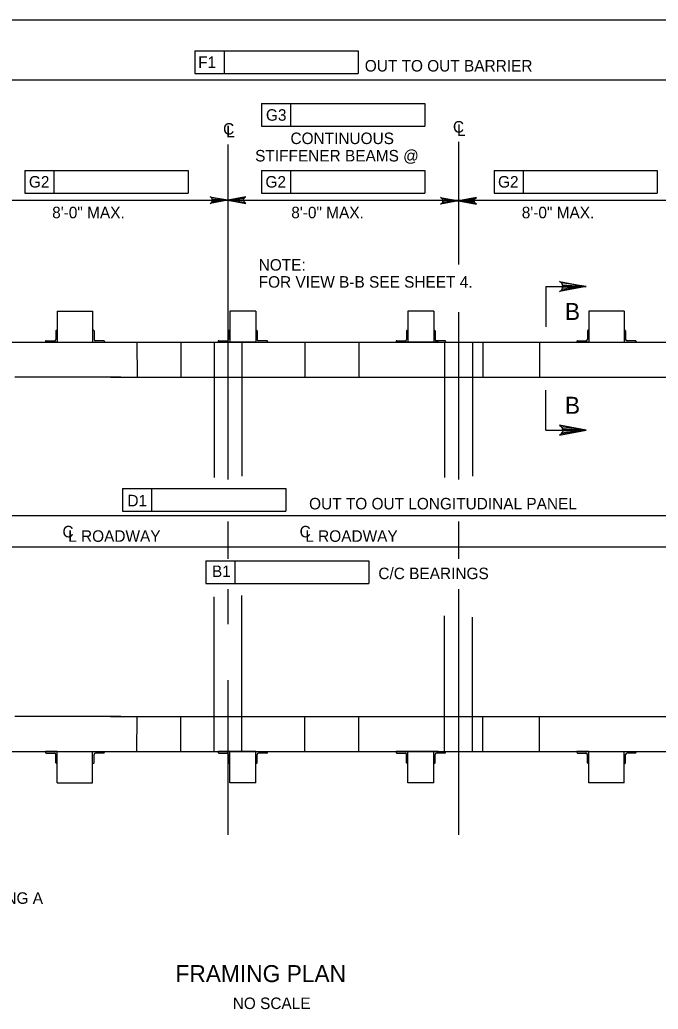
# Model space of a CAD drawing. Extents: x 638268 to 640277, y 295465 to 298435.
# Drawn here: x 639470.3 to 639636.6, y 297568.6 to 297826.5 of the extents above; entities that cross this region are included whole.
import ezdxf

# ---------------------------------------------------------------- set-up
doc = ezdxf.new("R2010")
doc.units = 0
doc.layers.add('2', color=7, linetype='Continuous')
doc.layers.add('4', color=7, linetype='Continuous')

msp = doc.modelspace()

# ---------------------------------------------------------------- linework, layer by layer
at = {"layer": '2'}
for p, q in [((639316.46, 297826.46), (640102.46, 297826.46)), ((639607.37, 297756.95), (639607.37, 297746.46)), ((639607.37, 297756.95), (639617.86, 297756.95)), ((639480.06, 297750.53), (639489.29, 297750.53)), ((639480.06, 297750.53), (639480.06, 297742.44)), ((639489.29, 297750.53), (639489.29, 297742.44)), ((639531.78, 297750.53), (639525.05, 297750.53)), ((639525.05, 297750.53), (639525.05, 297742.44)), ((639531.78, 297750.53), (639531.78, 297742.44)), ((639578.14, 297750.53), (639571.41, 297750.53)), ((639578.14, 297750.53), (639571.41, 297750.53)), ((639571.41, 297750.53), (639571.41, 297742.44)), ((639578.14, 297750.53), (639578.14, 297742.44)), ((639627.77, 297750.53), (639618.53, 297750.53)), ((639618.53, 297750.53), (639618.53, 297742.44)), ((639627.77, 297750.53), (639627.77, 297742.44)), ((639479.69, 297745.35), (639479.69, 297743.17)), ((639479.87, 297745.53), (639480.06, 297745.53)), ((639480.06, 297745.53), (639480.06, 297742.44)), ((639489.48, 297745.53), (639489.29, 297745.53)), ((639489.29, 297745.53), (639489.29, 297742.44)), ((639489.66, 297745.35), (639489.66, 297743.17)), ((639524.69, 297745.35), (639524.69, 297743.17)), ((639524.87, 297745.53), (639525.05, 297745.53)), ((639525.05, 297745.53), (639525.05, 297742.44)), ((639531.96, 297745.53), (639531.78, 297745.53)), ((639531.78, 297745.53), (639531.78, 297742.44)), ((639532.14, 297745.35), (639532.14, 297743.17)), ((639571.05, 297745.35), (639571.05, 297743.17)), ((639571.23, 297745.53), (639571.41, 297745.53)), ((639571.41, 297745.53), (639571.41, 297742.44)), ((639578.32, 297745.53), (639578.14, 297745.53)), ((639578.14, 297745.53), (639578.14, 297742.44)), ((639578.51, 297745.35), (639578.51, 297743.17)), ((639618.17, 297745.35), (639618.17, 297743.17)), ((639618.35, 297745.53), (639618.53, 297745.53)), ((639618.53, 297745.53), (639618.53, 297742.44)), ((639627.95, 297745.53), (639627.77, 297745.53)), ((639627.77, 297745.53), (639627.77, 297742.44)), ((639628.13, 297745.35), (639628.13, 297743.17)), ((639457.3, 297742.44), (639650.54, 297742.44)), ((639476.97, 297742.63), (639476.97, 297742.44)), ((639480.06, 297742.44), (639476.97, 297742.44)), ((639477.15, 297742.81), (639479.33, 297742.81)), ((639480.06, 297742.44), (639489.29, 297742.44)), ((639489.29, 297742.44), (639492.38, 297742.44)), ((639492.2, 297742.81), (639490.02, 297742.81)), ((639492.38, 297742.63), (639492.38, 297742.44)), ((639500.84, 297742.44), (639500.85, 297733.32)), ((639512.24, 297742.44), (639512.24, 297733.32)), ((639520.91, 297742.44), (639520.91, 297707.2)), ((639521.96, 297742.63), (639521.96, 297742.44)), ((639525.05, 297742.44), (639521.96, 297742.44)), ((639522.14, 297742.81), (639524.32, 297742.81)), ((639531.78, 297742.44), (639525.05, 297742.44)), ((639528.12, 297742.44), (639528.12, 297707.55)), ((639531.78, 297742.44), (639534.87, 297742.44)), ((639534.69, 297742.81), (639532.51, 297742.81)), ((639534.87, 297742.63), (639534.87, 297742.44)), ((639544.58, 297742.44), (639544.58, 297733.32)), ((639558.61, 297742.44), (639558.61, 297733.32)), ((639568.32, 297742.63), (639568.32, 297742.44)), ((639571.41, 297742.44), (639568.32, 297742.44)), ((639568.51, 297742.81), (639570.69, 297742.81)), ((639579.4, 297742.44), (639570.16, 297742.44)), ((639578.14, 297742.44), (639571.41, 297742.44)), ((639578.14, 297742.44), (639581.23, 297742.44)), ((639581.05, 297742.81), (639578.87, 297742.81)), ((639580.99, 297742.44), (639580.99, 297707.2)), ((639581.23, 297742.63), (639581.23, 297742.44)), ((639588.2, 297742.44), (639588.2, 297707.55)), ((639590.95, 297742.44), (639590.95, 297733.32)), ((639605.73, 297742.44), (639605.73, 297733.32)), ((639615.44, 297742.63), (639615.44, 297742.44)), ((639618.53, 297742.44), (639615.44, 297742.44)), ((639615.63, 297742.81), (639617.81, 297742.81)), ((639618.54, 297742.44), (639627.77, 297742.44)), ((639627.77, 297742.44), (639630.86, 297742.44)), ((639630.68, 297742.81), (639628.5, 297742.81)), ((639630.86, 297742.63), (639630.86, 297742.44)), ((639496.62, 297733.32), (639468.98, 297733.32)), ((639493.95, 297733.32), (639638.86, 297733.32)), ((639607.37, 297719.47), (639607.37, 297729.96)), ((639607.37, 297719.47), (639617.86, 297719.47)), ((639520.91, 297635.88), (639520.91, 297676.03)), ((639528.12, 297635.88), (639528.12, 297676.44)), ((639580.99, 297635.88), (639580.99, 297671.12)), ((639588.2, 297635.88), (639588.2, 297670.78)), ((639496.62, 297644.84), (639468.98, 297644.84)), ((639493.95, 297644.84), (639638.86, 297644.84)), ((639500.84, 297635.72), (639500.85, 297644.84)), ((639512.24, 297635.72), (639512.24, 297644.84)), ((639544.58, 297635.72), (639544.58, 297644.84)), ((639558.61, 297635.72), (639558.61, 297644.84)), ((639590.95, 297635.72), (639590.95, 297644.84)), ((639605.73, 297635.72), (639605.73, 297644.84)), ((639457.3, 297635.72), (639650.54, 297635.72)), ((639476.97, 297635.54), (639476.97, 297635.72)), ((639480.06, 297635.72), (639476.97, 297635.72)), ((639477.15, 297635.35), (639479.33, 297635.35)), ((639479.69, 297632.81), (639479.69, 297634.99)), ((639480.06, 297635.72), (639489.29, 297635.72)), ((639480.06, 297632.63), (639480.06, 297635.72)), ((639480.06, 297627.63), (639480.06, 297635.72)), ((639489.29, 297635.72), (639492.38, 297635.72)), ((639489.29, 297632.63), (639489.29, 297635.72)), ((639489.29, 297627.63), (639489.29, 297635.72)), ((639489.66, 297632.81), (639489.66, 297634.99)), ((639492.2, 297635.35), (639490.02, 297635.35)), ((639492.38, 297635.54), (639492.38, 297635.72)), ((639521.96, 297635.54), (639521.96, 297635.72)), ((639525.05, 297635.72), (639521.96, 297635.72)), ((639522.14, 297635.35), (639524.32, 297635.35)), ((639524.69, 297632.81), (639524.69, 297634.99)), ((639531.78, 297635.72), (639525.05, 297635.72)), ((639525.05, 297632.63), (639525.05, 297635.72)), ((639525.05, 297627.63), (639525.05, 297635.72)), ((639531.78, 297632.63), (639531.78, 297635.72)), ((639531.78, 297635.72), (639534.87, 297635.72)), ((639531.78, 297627.63), (639531.78, 297635.72)), ((639532.14, 297632.81), (639532.14, 297634.99)), ((639534.69, 297635.35), (639532.51, 297635.35)), ((639534.87, 297635.54), (639534.87, 297635.72)), ((639568.32, 297635.54), (639568.32, 297635.72)), ((639571.41, 297635.72), (639568.32, 297635.72)), ((639568.51, 297635.35), (639570.69, 297635.35)), ((639579.4, 297635.72), (639570.16, 297635.72)), ((639571.05, 297632.81), (639571.05, 297634.99)), ((639578.14, 297635.72), (639571.41, 297635.72)), ((639571.41, 297632.63), (639571.41, 297635.72)), ((639571.41, 297627.63), (639571.41, 297635.72)), ((639578.14, 297632.63), (639578.14, 297635.72)), ((639578.14, 297635.72), (639581.23, 297635.72)), ((639578.14, 297627.63), (639578.14, 297635.72)), ((639578.51, 297632.81), (639578.51, 297634.99)), ((639581.05, 297635.35), (639578.87, 297635.35)), ((639581.23, 297635.54), (639581.23, 297635.72)), ((639615.44, 297635.54), (639615.44, 297635.72)), ((639618.53, 297635.72), (639615.44, 297635.72)), ((639615.63, 297635.35), (639617.81, 297635.35)), ((639618.17, 297632.81), (639618.17, 297634.99)), ((639618.53, 297632.63), (639618.53, 297635.72)), ((639618.53, 297627.63), (639618.53, 297635.72)), ((639618.54, 297635.72), (639627.77, 297635.72)), ((639627.77, 297632.63), (639627.77, 297635.72)), ((639627.77, 297635.72), (639630.86, 297635.72)), ((639627.77, 297627.63), (639627.77, 297635.72)), ((639628.13, 297632.81), (639628.13, 297634.99)), ((639630.68, 297635.35), (639628.5, 297635.35)), ((639630.86, 297635.54), (639630.86, 297635.72)), ((639479.87, 297632.63), (639480.06, 297632.63)), ((639489.48, 297632.63), (639489.29, 297632.63)), ((639524.87, 297632.63), (639525.05, 297632.63)), ((639531.96, 297632.63), (639531.78, 297632.63)), ((639571.23, 297632.63), (639571.41, 297632.63)), ((639578.32, 297632.63), (639578.14, 297632.63)), ((639618.35, 297632.63), (639618.53, 297632.63)), ((639627.95, 297632.63), (639627.77, 297632.63)), ((639480.06, 297627.63), (639489.29, 297627.63)), ((639531.78, 297627.63), (639525.05, 297627.63)), ((639578.14, 297627.63), (639571.41, 297627.63)), ((639578.14, 297627.63), (639571.41, 297627.63)), ((639627.77, 297627.63), (639618.53, 297627.63))]:
    msp.add_line(p, q, dxfattribs=at)
for points in [[(639617.86, 297756.95), (639610.87, 297755.64), (639611.4, 297756.01), (639611.68, 297756.48), (639611.76, 297756.95), (639611.68, 297757.41), (639611.4, 297757.88), (639610.87, 297758.25), (639617.86, 297756.95), (639611.4, 297757.88), (639611.68, 297757.41), (639617.86, 297756.95), (639611.76, 297756.95), (639611.68, 297756.48), (639617.86, 297756.95), (639611.4, 297756.01)], [(639617.86, 297719.47), (639610.87, 297720.78), (639611.4, 297720.41), (639611.68, 297719.94), (639611.76, 297719.47), (639611.68, 297719.01), (639611.4, 297718.54), (639610.87, 297718.17), (639617.86, 297719.47), (639611.4, 297718.54), (639611.68, 297719.01), (639617.86, 297719.47), (639611.76, 297719.47), (639611.68, 297719.94), (639617.86, 297719.47), (639611.4, 297720.41)]]:
    msp.add_lwpolyline(points, dxfattribs=at)
for centre, radius, start, end in [((639479.87, 297745.35), 0.182, 90, 179.9984), ((639489.48, 297745.35), 0.182, 0.0016, 90), ((639524.87, 297745.35), 0.182, 90, 179.9984), ((639531.96, 297745.35), 0.182, 0.0016, 90), ((639571.23, 297745.35), 0.182, 90, 179.9984), ((639578.32, 297745.35), 0.182, 0.0016, 90), ((639618.35, 297745.35), 0.182, 90, 179.9984), ((639627.95, 297745.35), 0.182, 0.0016, 90), ((639477.15, 297742.63), 0.182, 90, 179.9984), ((639479.33, 297743.17), 0.364, 270, 359.9984), ((639490.02, 297743.17), 0.364, 180.0016, 270), ((639492.2, 297742.63), 0.182, 0.0016, 90), ((639522.14, 297742.63), 0.182, 90, 179.9984), ((639524.32, 297743.17), 0.364, 270, 359.9984), ((639532.51, 297743.17), 0.364, 180.0016, 270), ((639534.69, 297742.63), 0.182, 0.0016, 90), ((639568.51, 297742.63), 0.182, 90, 179.9984), ((639570.69, 297743.17), 0.364, 270, 359.9984), ((639578.87, 297743.17), 0.364, 180.0016, 270), ((639581.05, 297742.63), 0.182, 0.0016, 90), ((639615.63, 297742.63), 0.182, 90, 179.9984), ((639617.81, 297743.17), 0.364, 270, 359.9984), ((639628.5, 297743.17), 0.364, 180.0016, 270), ((639630.68, 297742.63), 0.182, 0.0016, 90), ((639477.15, 297635.54), 0.182, 180.0016, 270), ((639479.33, 297634.99), 0.364, 0.0016, 90), ((639490.02, 297634.99), 0.364, 90, 179.9984), ((639492.2, 297635.54), 0.182, 270, 359.9984), ((639522.14, 297635.54), 0.182, 180.0016, 270), ((639524.32, 297634.99), 0.364, 0.0016, 90), ((639532.51, 297634.99), 0.364, 90, 179.9984), ((639534.69, 297635.54), 0.182, 270, 359.9984), ((639568.51, 297635.54), 0.182, 180.0016, 270), ((639570.69, 297634.99), 0.364, 0.0016, 90), ((639578.87, 297634.99), 0.364, 90, 179.9984), ((639581.05, 297635.54), 0.182, 270, 359.9984), ((639615.63, 297635.54), 0.182, 180.0016, 270), ((639617.81, 297634.99), 0.364, 0.0016, 90), ((639628.5, 297634.99), 0.364, 90, 179.9984), ((639630.68, 297635.54), 0.182, 270, 359.9984), ((639479.87, 297632.81), 0.182, 180.0016, 270), ((639489.48, 297632.81), 0.182, 270, 359.9984), ((639524.87, 297632.81), 0.182, 180.0016, 270), ((639531.96, 297632.81), 0.182, 270, 359.9984), ((639571.23, 297632.81), 0.182, 180.0016, 270), ((639578.32, 297632.81), 0.182, 270, 359.9984), ((639618.35, 297632.81), 0.182, 180.0016, 270), ((639627.95, 297632.81), 0.182, 270, 359.9984)]:
    msp.add_arc(centre, radius, start, end, dxfattribs=at)
at = {"layer": '4'}
for p, q in [((639515.95, 297818.36), (639558.47, 297818.36)), ((639515.95, 297818.36), (639515.95, 297812.46)), ((639523.51, 297818.36), (639523.51, 297812.46)), ((639558.47, 297818.36), (639558.47, 297812.46)), ((639515.95, 297812.46), (639558.47, 297812.46)), ((639457.3, 297810.78), (639649.71, 297810.78)), ((639533.27, 297804.6), (639575.79, 297804.6)), ((639533.27, 297804.6), (639533.27, 297798.7)), ((639540.83, 297804.6), (639540.83, 297798.7)), ((639575.79, 297804.6), (639575.79, 297798.7)), ((639533.27, 297798.7), (639575.79, 297798.7)), ((639524.52, 297793.97), (639524.52, 297706.67)), ((639584.59, 297794.64), (639584.59, 297762.7)), ((639471.64, 297787.18), (639514.16, 297787.18)), ((639471.64, 297787.18), (639471.64, 297781.28)), ((639479.2, 297787.18), (639479.2, 297781.28)), ((639514.16, 297787.18), (639514.16, 297781.28)), ((639533.27, 297787.18), (639575.79, 297787.18)), ((639533.27, 297787.18), (639533.27, 297781.28)), ((639540.83, 297787.18), (639540.83, 297781.28)), ((639575.79, 297787.18), (639575.79, 297781.28)), ((639593.86, 297787.18), (639636.38, 297787.18)), ((639593.86, 297787.18), (639593.86, 297781.28)), ((639601.42, 297787.18), (639601.42, 297781.28)), ((639636.38, 297787.18), (639636.38, 297781.28)), ((639471.64, 297781.28), (639514.16, 297781.28)), ((639533.27, 297781.28), (639575.79, 297781.28)), ((639593.86, 297781.28), (639636.38, 297781.28)), ((639462.25, 297779.47), (639522.17, 297779.47)), ((639522.17, 297779.47), (639583.42, 297779.47)), ((639583.42, 297779.47), (639583.42, 297779.47)), ((639583.42, 297779.47), (639644.67, 297779.47)), ((639584.59, 297750.26), (639584.59, 297706.67)), ((639497.1, 297704.33), (639539.62, 297704.33)), ((639497.1, 297704.33), (639497.1, 297698.43)), ((639504.66, 297704.33), (639504.66, 297698.43)), ((639539.62, 297704.33), (639539.62, 297698.43)), ((639497.1, 297698.43), (639539.62, 297698.43)), ((639457.52, 297697.23), (639650.54, 297697.23)), ((639524.52, 297695.69), (639524.52, 297685.98)), ((639584.59, 297695.69), (639584.59, 297685.98)), ((639439.93, 297689.08), (639696.71, 297689.08)), ((639518.75, 297685.45), (639561.27, 297685.45)), ((639518.75, 297685.45), (639518.75, 297679.54)), ((639526.31, 297685.45), (639526.31, 297679.54)), ((639561.27, 297685.45), (639561.27, 297679.54)), ((639518.75, 297679.54), (639561.27, 297679.54)), ((639524.52, 297678.02), (639524.52, 297668.98)), ((639584.59, 297678.02), (639584.59, 297614.05)), ((639524.52, 297654.31), (639524.52, 297614.05))]:
    msp.add_line(p, q, dxfattribs=at)
for points in [[(639524.52, 297779.47), (639519.86, 297778.6), (639520.22, 297778.85), (639520.4, 297779.16), (639520.46, 297779.47), (639520.4, 297779.79), (639520.22, 297780.1), (639519.86, 297780.35), (639524.52, 297779.47), (639520.22, 297780.1), (639520.4, 297779.79), (639524.52, 297779.47), (639520.46, 297779.47), (639520.4, 297779.16), (639524.52, 297779.47), (639520.22, 297778.85)], [(639524.52, 297779.47), (639529.18, 297778.6), (639528.82, 297778.85), (639528.63, 297779.16), (639528.58, 297779.47), (639528.63, 297779.79), (639528.82, 297780.1), (639529.18, 297780.35), (639524.52, 297779.47), (639528.82, 297780.1), (639528.63, 297779.79), (639524.52, 297779.47), (639528.58, 297779.47), (639528.63, 297779.16), (639524.52, 297779.47), (639528.82, 297778.85)], [(639584.59, 297779.26), (639579.93, 297778.39), (639580.29, 297778.64), (639580.48, 297778.95), (639580.53, 297779.26), (639580.48, 297779.58), (639580.29, 297779.89), (639579.93, 297780.14), (639584.59, 297779.26), (639580.29, 297779.89), (639580.48, 297779.58), (639584.59, 297779.26), (639580.53, 297779.26), (639580.48, 297778.95), (639584.59, 297779.26), (639580.29, 297778.64)], [(639584.59, 297779.26), (639589.25, 297778.39), (639588.9, 297778.64), (639588.71, 297778.95), (639588.66, 297779.26), (639588.71, 297779.58), (639588.9, 297779.89), (639589.25, 297780.14), (639584.59, 297779.26), (639588.9, 297779.89), (639588.71, 297779.58), (639584.59, 297779.26), (639588.66, 297779.26), (639588.71, 297778.95), (639584.59, 297779.26), (639588.9, 297778.64)]]:
    msp.add_lwpolyline(points, dxfattribs=at)

# ---------------------------------------------------------------- texts
for s, height, rotation, p in [('F1', 3, 359.9382, (639516.78, 297813.91)), ('G3', 3, 359.9382, (639534.43, 297800.15)), ('G2', 3, 359.9382, (639472.68, 297782.73)), ('G2', 3, 359.9382, (639534.3, 297782.73)), ('G2', 3, 359.9382, (639594.89, 297782.73)), ('8\'-0" MAX.', 3, 359.9382, (639478.74, 297774.73)), ('8\'-0" MAX.', 3, 359.9382, (639541.03, 297774.73)), ('8\'-0" MAX.', 3, 359.9382, (639601.07, 297774.73)), ('B', 4.43, 360, (639612.31, 297748.22)), ('B', 4.43, 360, (639612.31, 297723.77)), ('D1', 3, 359.9382, (639498.35, 297699.65)), ('B1', 3, 359.9382, (639520.37, 297681.23))]:
    msp.add_text(s, height=height, rotation=rotation, dxfattribs=at).set_placement(p)
for s, height, p in [('OUT TO OUT BARRIER ', 3, (639560.18, 297812.97)), ('C', 3, (639523.28, 297796.53)), ('C', 3, (639583.15, 297797.06)), ('L', 3, (639584.22, 297796.19)), ('L', 3, (639524.07, 297795.86)), ('CONTINUOUS', 3, (639540.82, 297794.06)), ('STIFFENER BEAMS @', 3, (639531.62, 297789.53)), ('NOTE:', 3, (639532.54, 297761.08)), ('FOR VIEW B-B SEE SHEET 4.', 3, (639532.54, 297756.64)), ('OUT TO OUT LONGITUDINAL PANEL', 3, (639545.67, 297698.85)), ('C', 3, (639481.43, 297691.56)), ('L ROADWAY', 3, (639482.91, 297690.4)), ('C', 3, (639543.2, 297691.56)), ('L ROADWAY', 3, (639544.68, 297690.4)), ('C/C BEARINGS', 3, (639563.72, 297680.67)), ('WING A', 3, (639461.65, 297596.05)), ('FRAMING PLAN', 4.4292, (639510.87, 297575.65)), ('NO SCALE', 3, (639525.77, 297568.63))]:
    msp.add_text(s, height=height, dxfattribs=at).set_placement(p)

doc.saveas('drawing.dxf')
